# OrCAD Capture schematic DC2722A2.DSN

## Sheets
1 PAGE3: size B; title: DSP6713 SYSTEM; rev: V1.0; company: WITH DIGITAL POWER MANAGEMENT; note: DUAL STEP-DOWN uMODULE REGULATOR
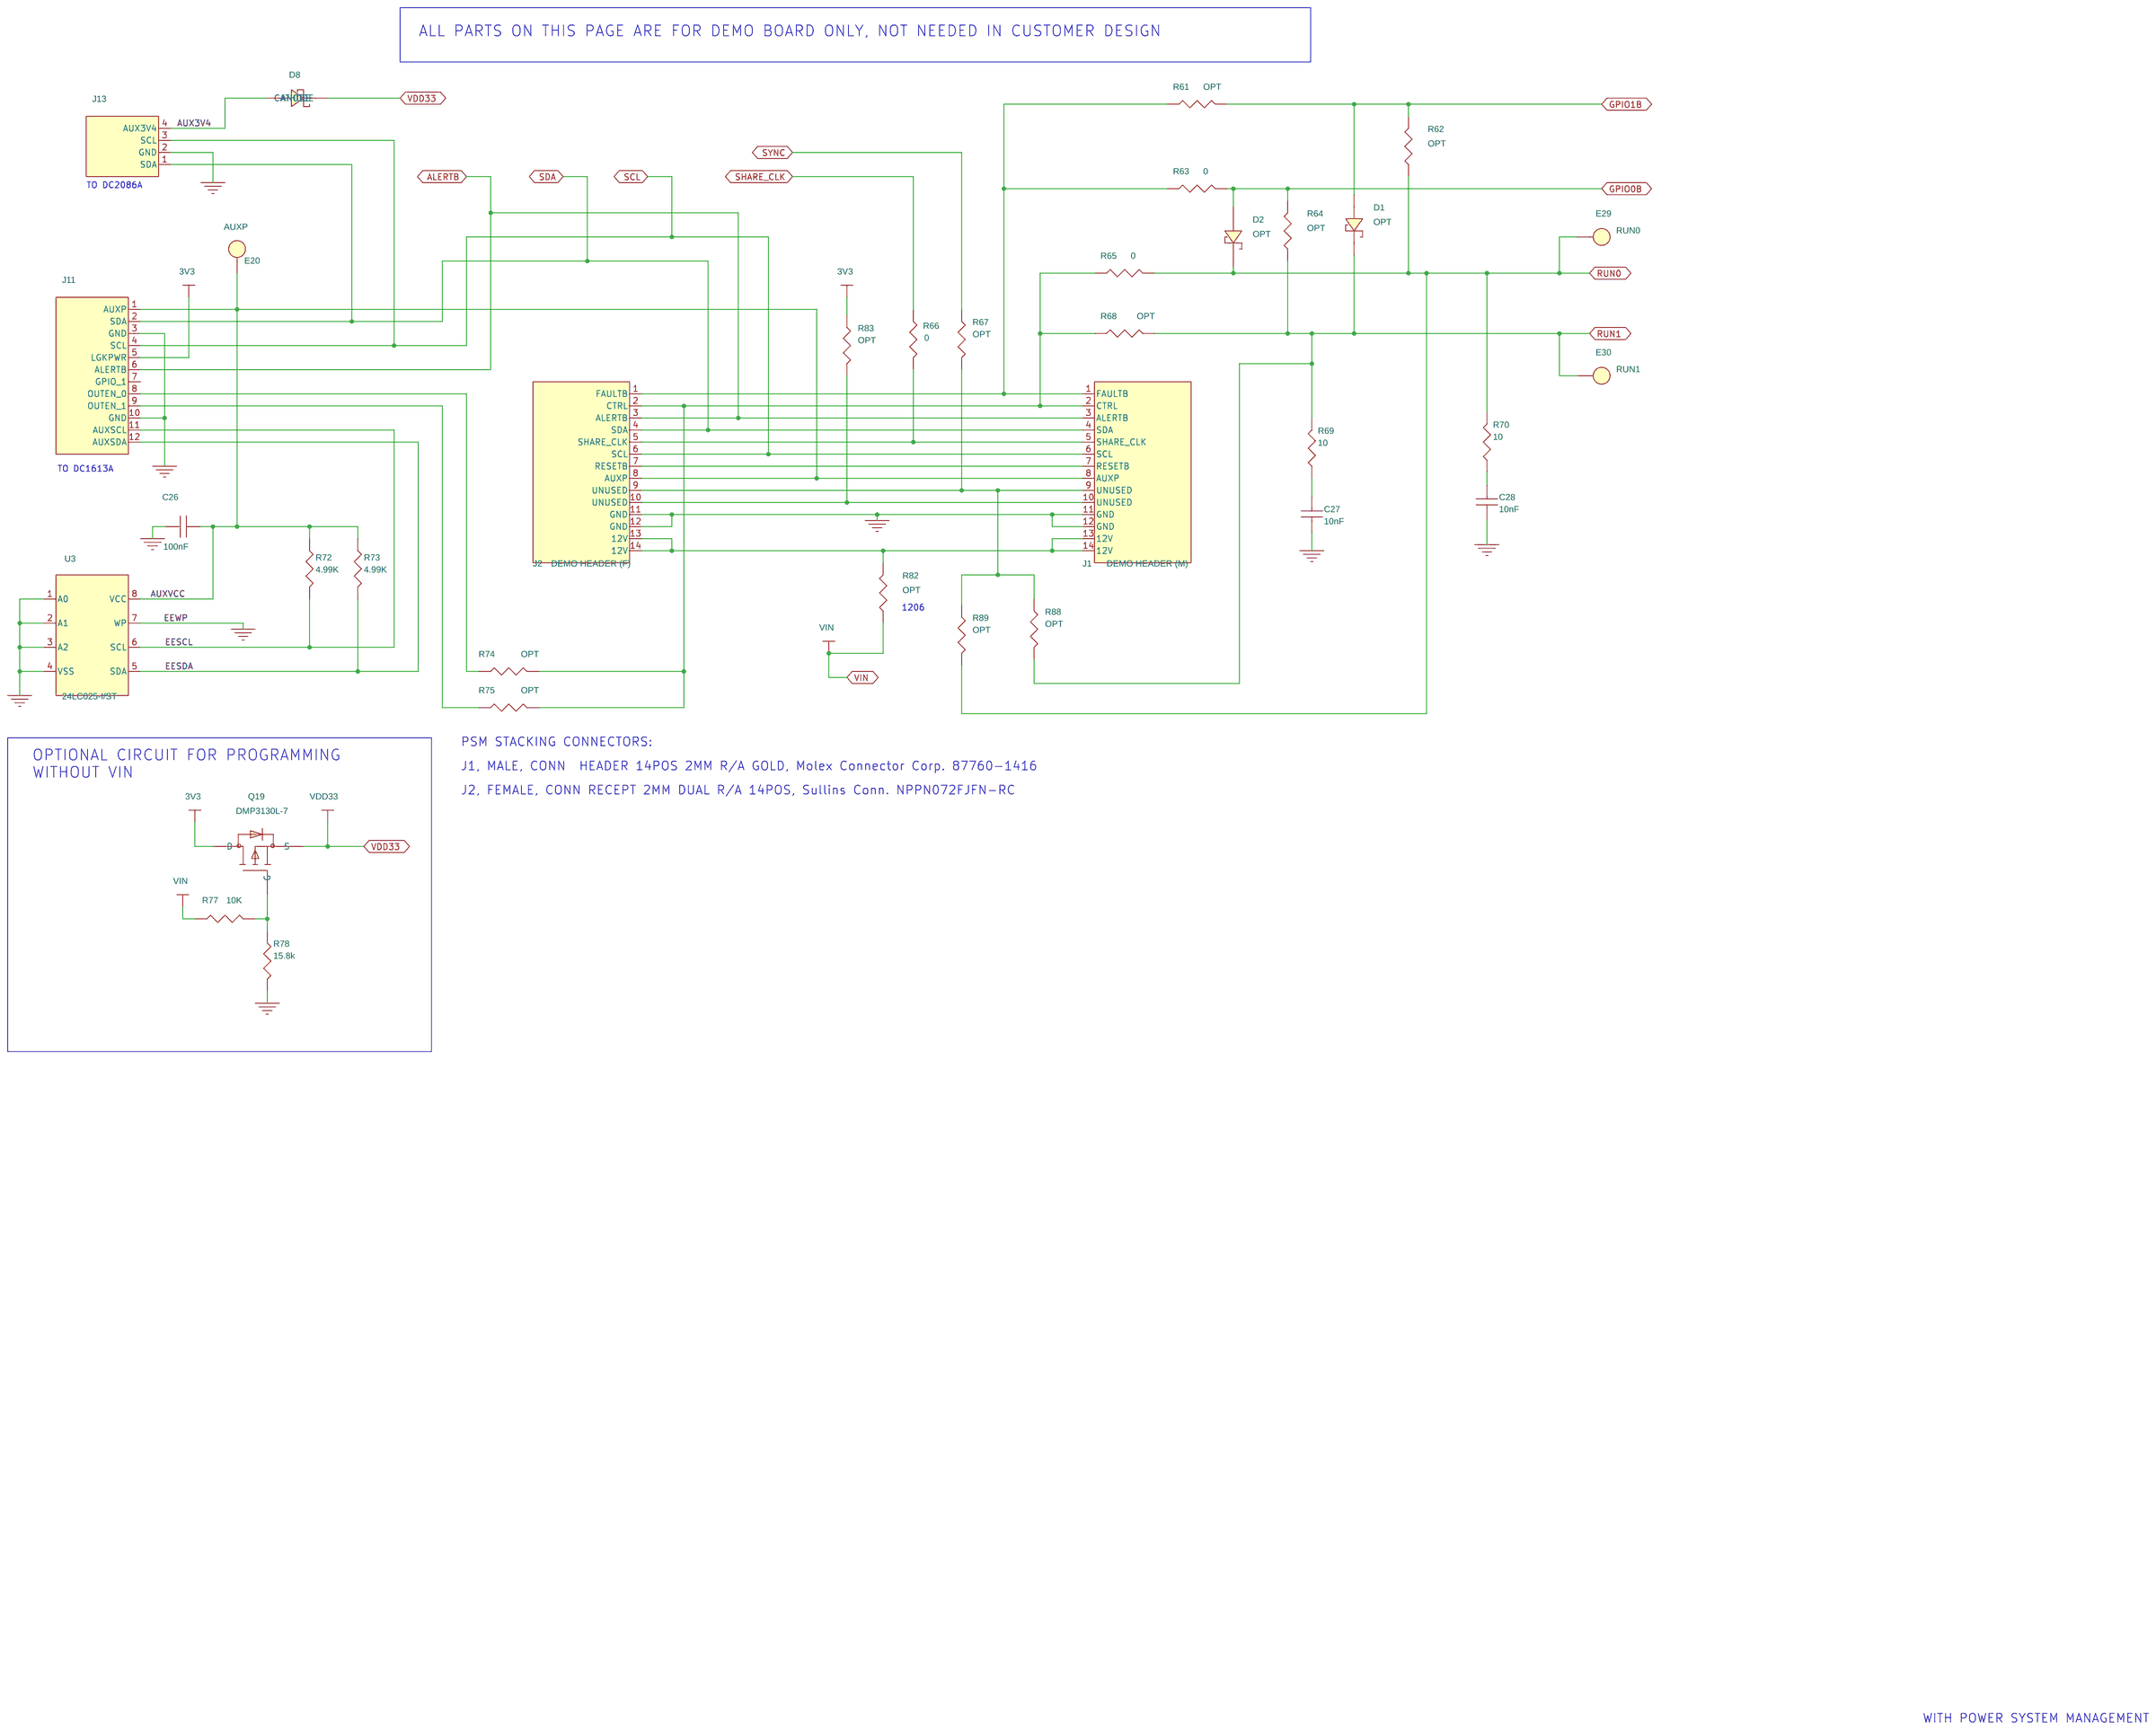
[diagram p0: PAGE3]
2 PAGE1: size C
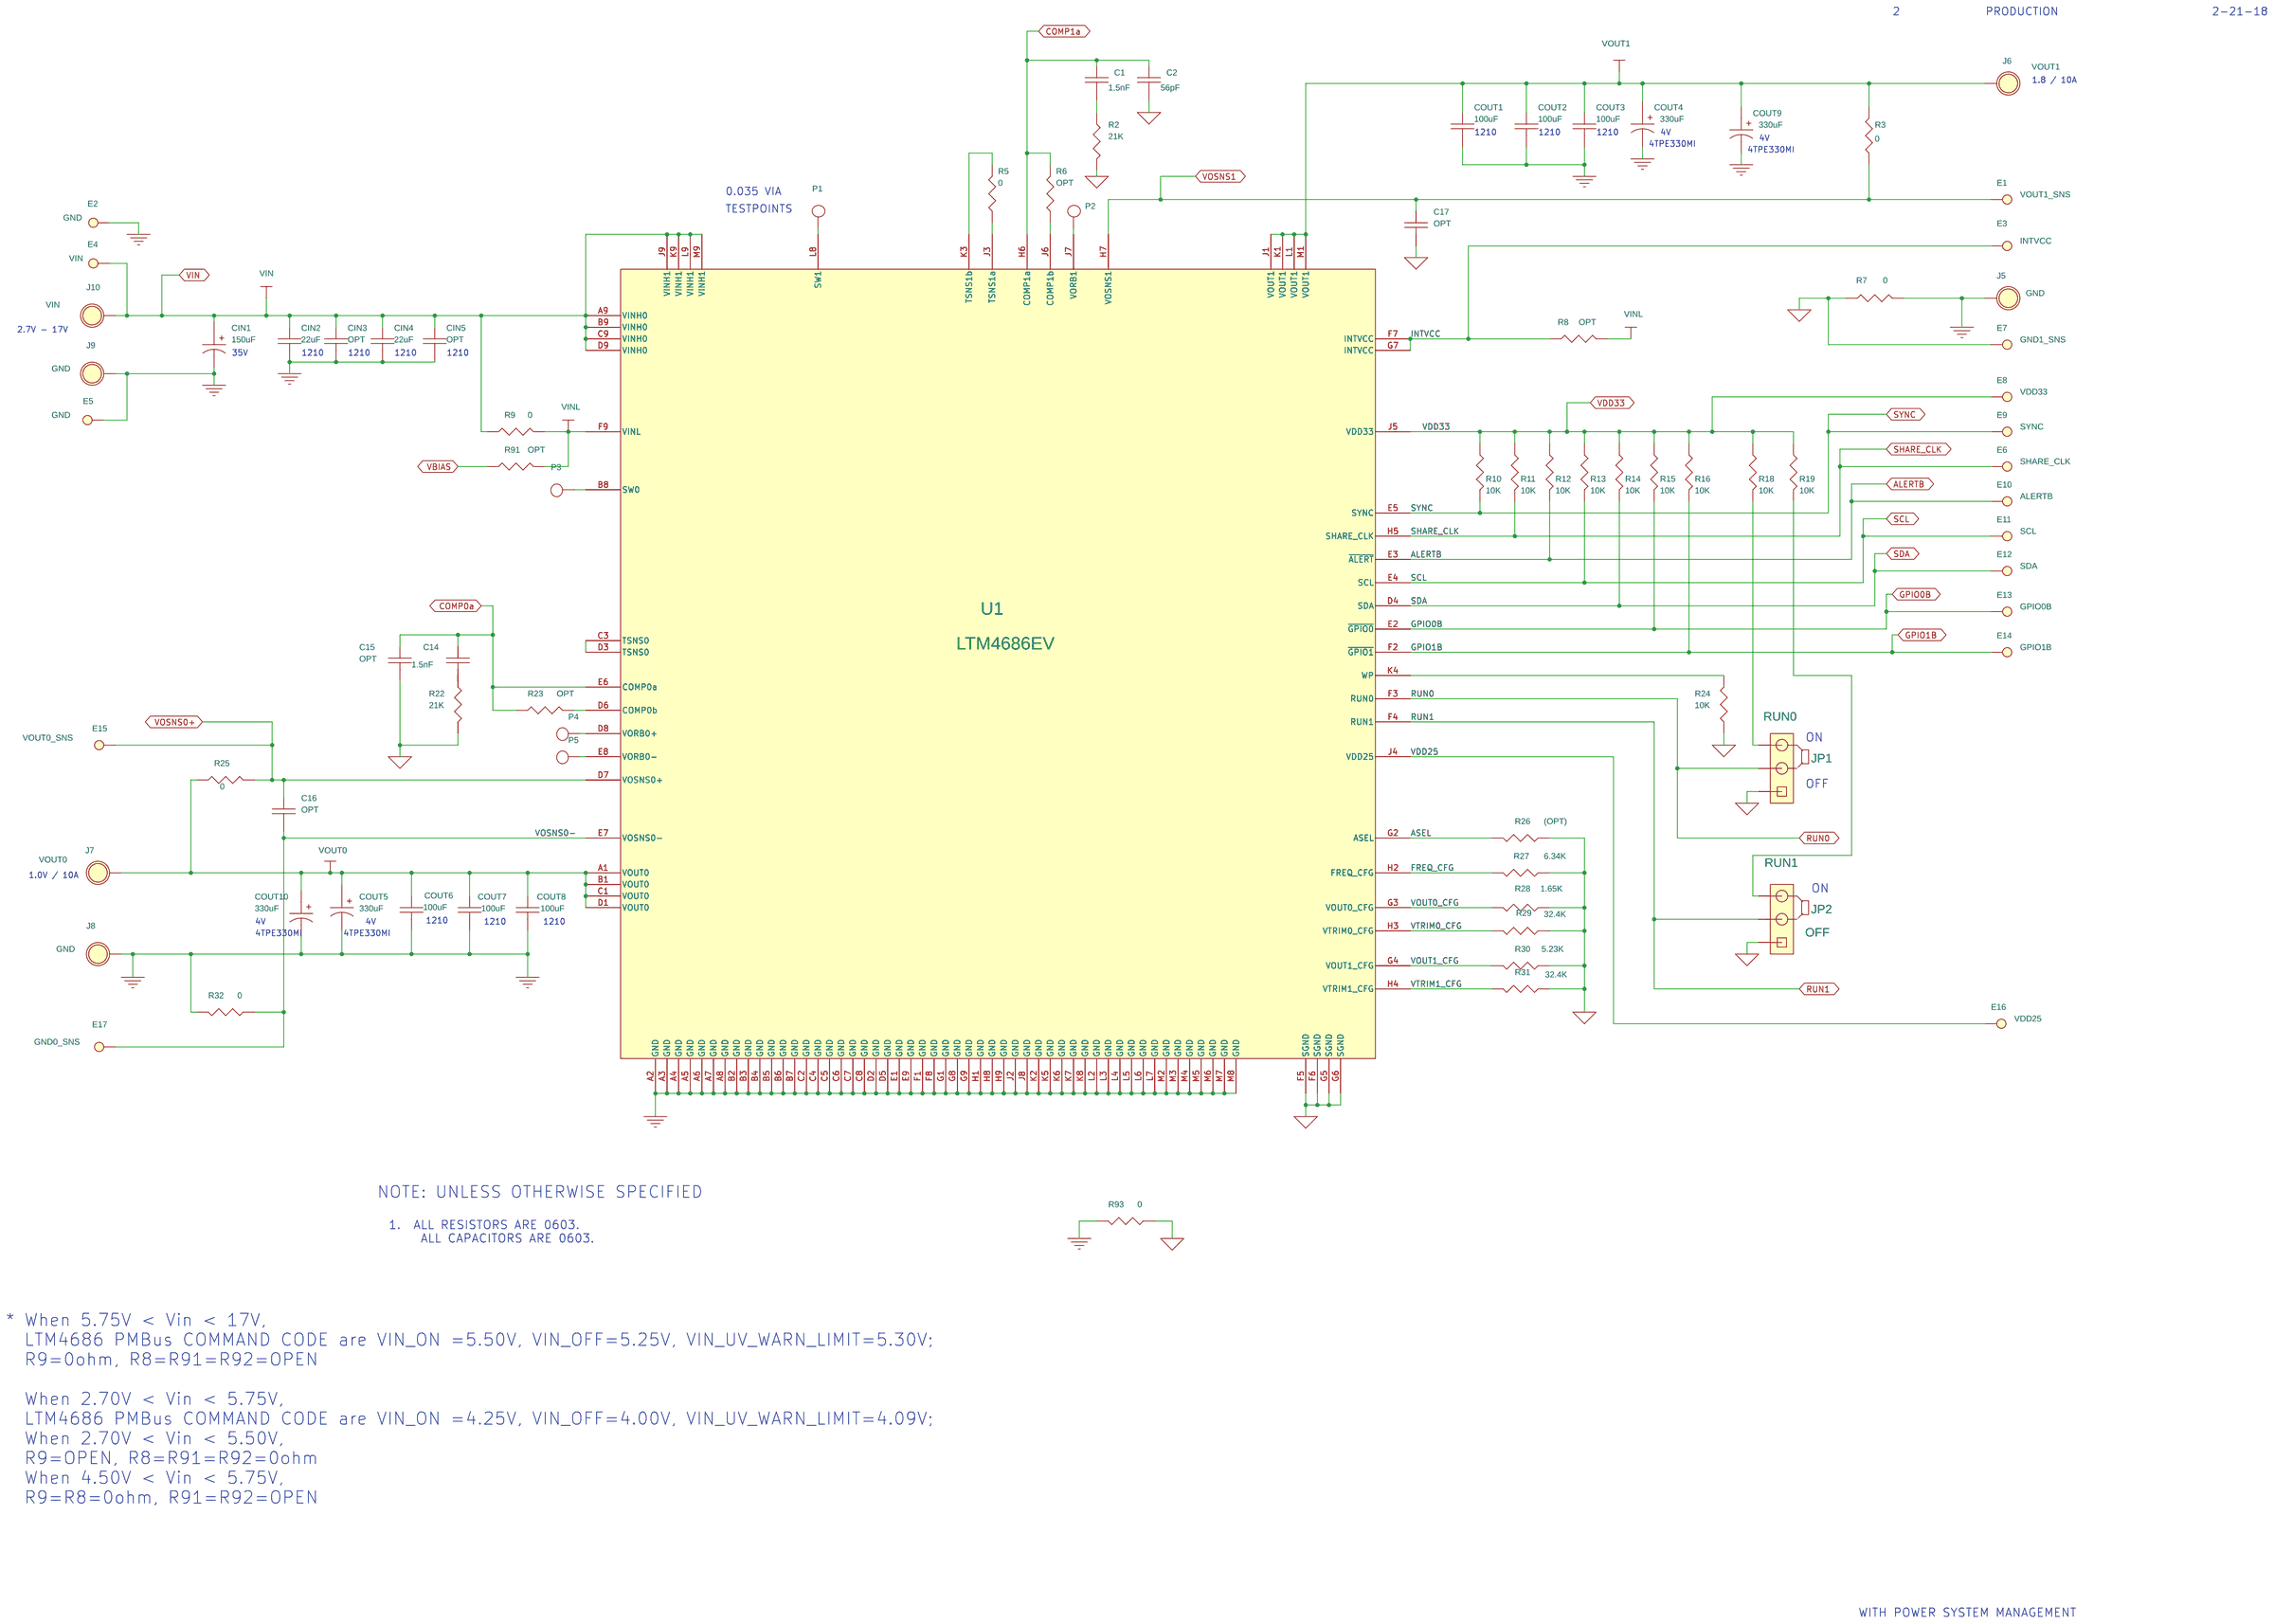
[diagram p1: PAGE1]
3 PAGE2: size Custom
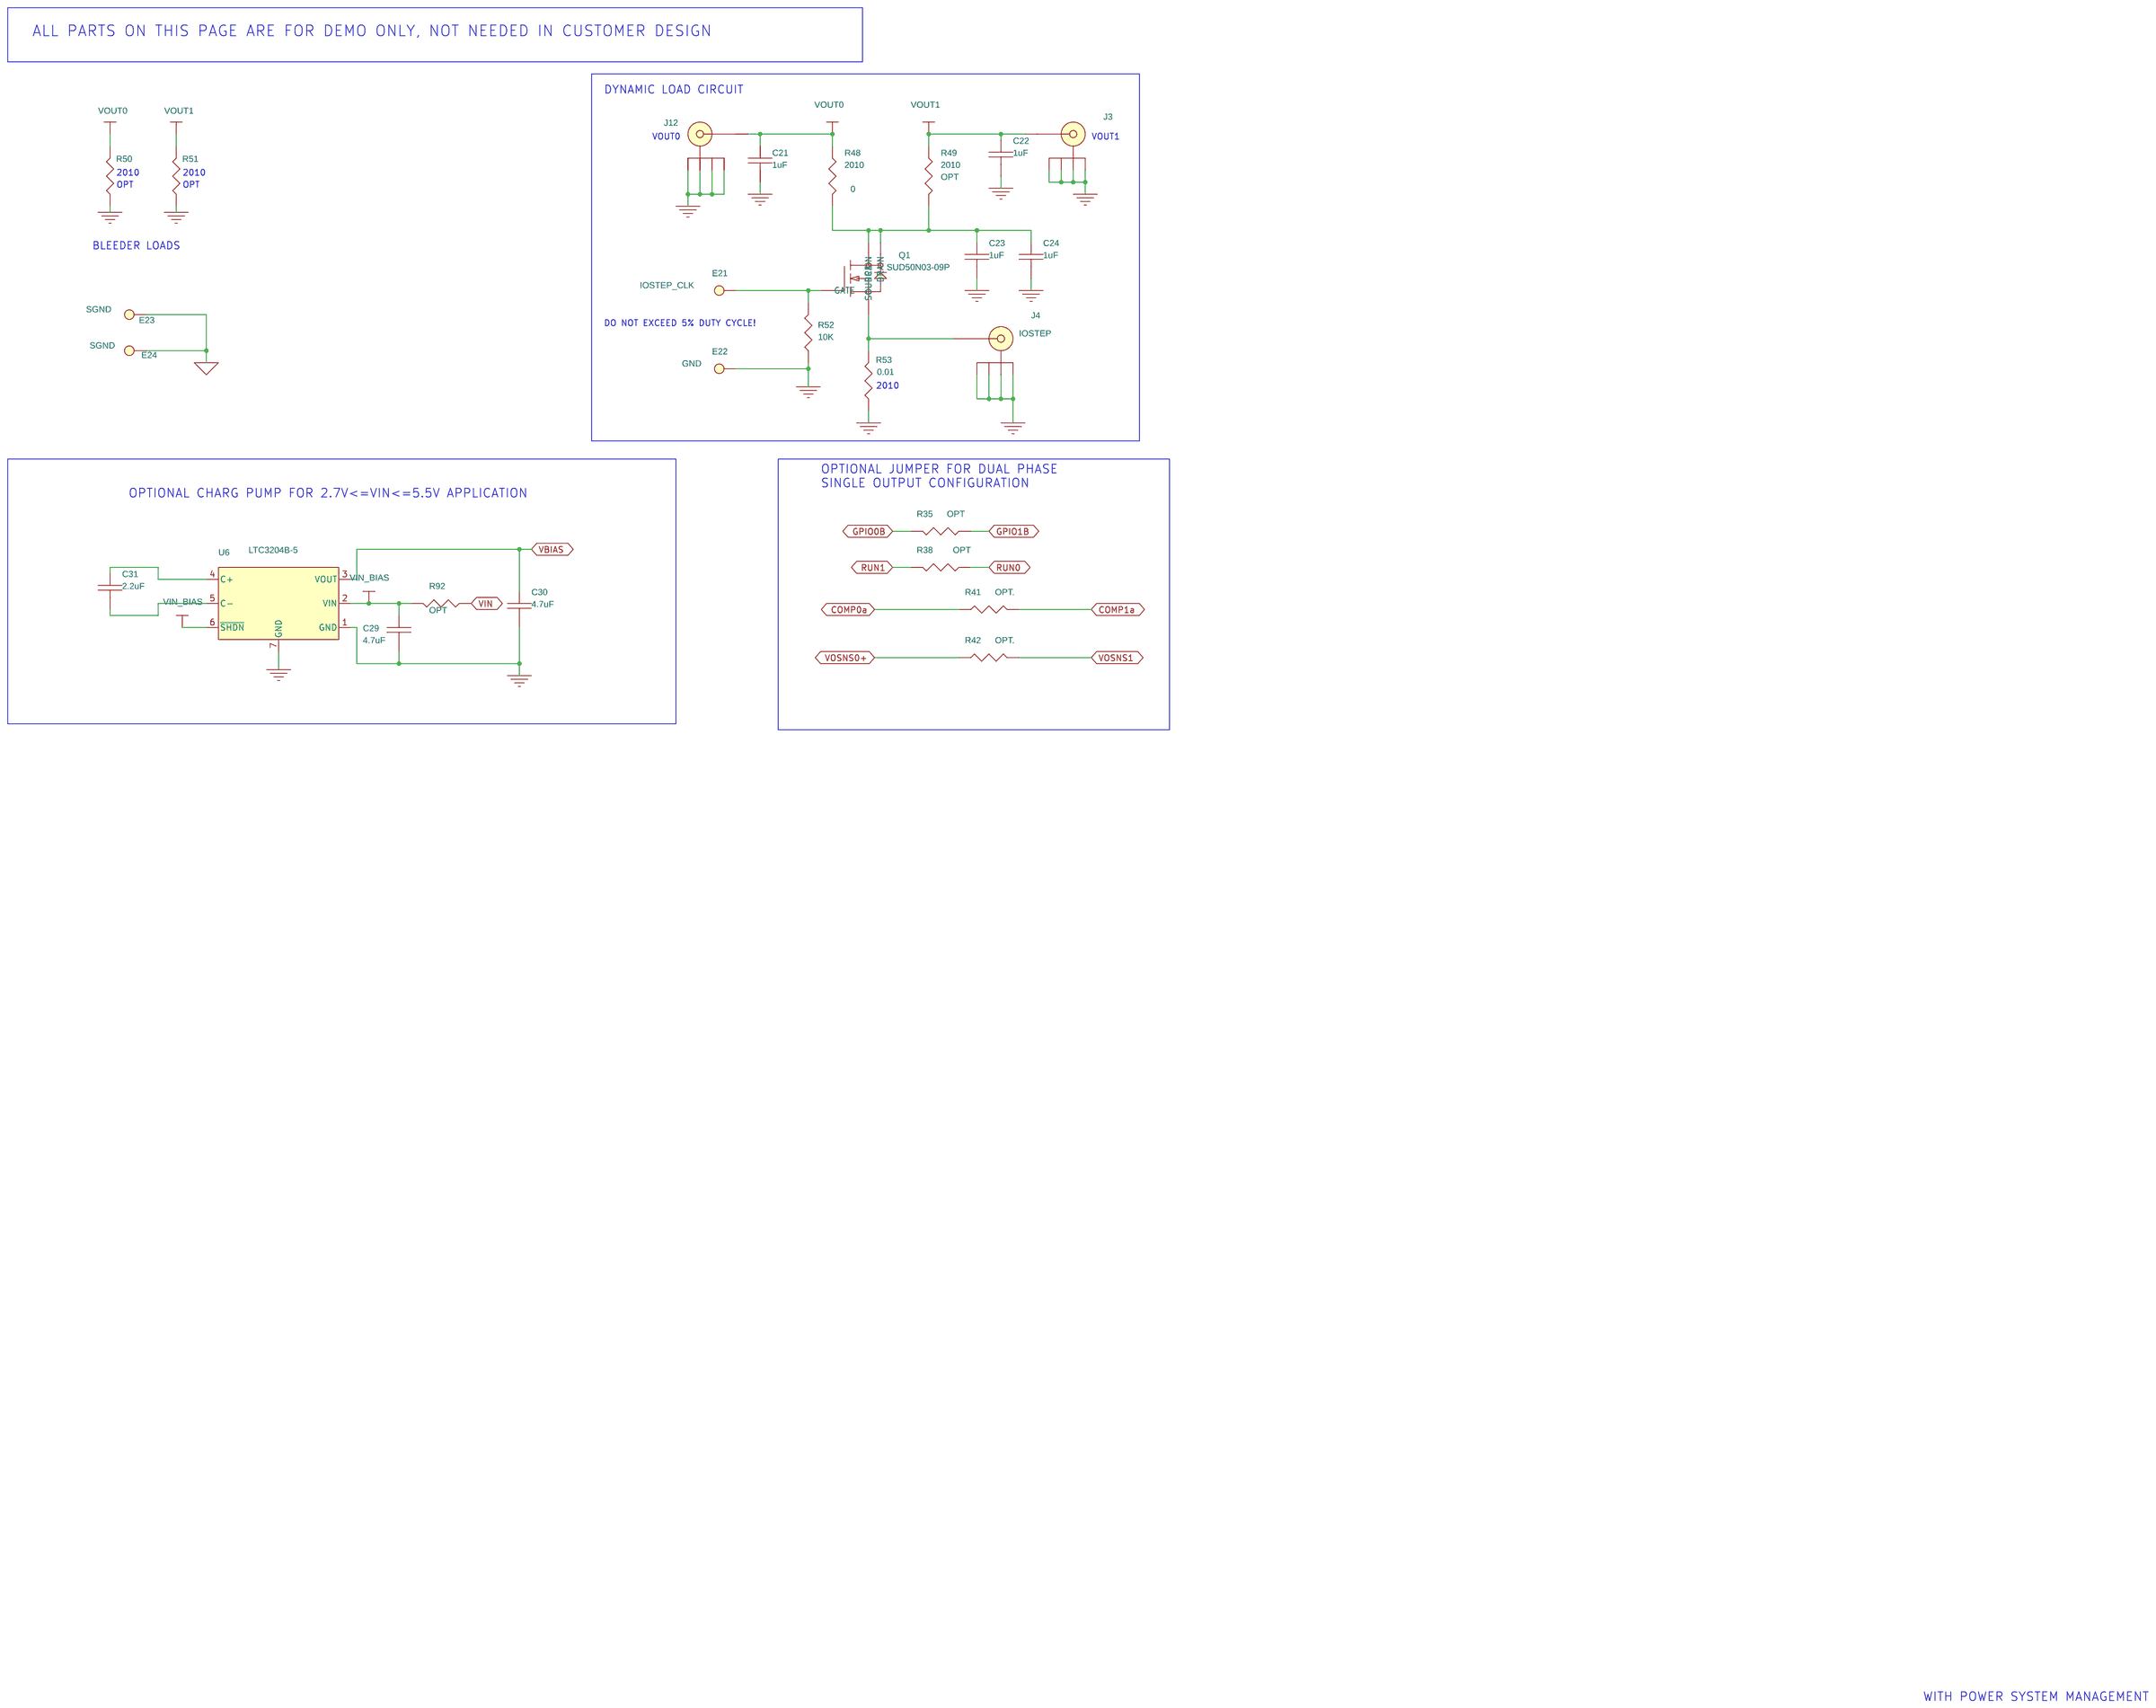
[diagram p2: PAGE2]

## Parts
sheet PAGE1
C1  1.5nF  [0603]
C2  56pF  [0603]
C14  1.5nF  [0603]
C15  OPT  [0603]
C16  OPT  [0603]
C17  OPT  [0603]
CIN1  150uF  [SANYO\8X10]
CIN2  22uF  [1210]
CIN3  OPT  [1210]
CIN4  22uF  [1210]
CIN5  OPT  [1210]
COUT1  100uF  [1210]
COUT2  100uF  [1210]
COUT3  100uF  [1210]
COUT4  330uF  [D3L]
COUT5  330uF  [D3L]
COUT6  100uF  [1210]
COUT7  100uF  [1210]
COUT8  100uF  [1210]
COUT9  330uF  [D3L]
COUT10  330uF  [D3L]
E1  TURRETS  [TURRETS]
E2  GND  [TURRETS]
E3  INTVCC  [TURRETS]
E4  TURRETS  [TURRETS]
E5  GND  [TURRETS]
E6  TURRETS  [TURRETS]
E7  TURRETS  [TURRETS]
E8  VDD33  [TURRETS]
E9  TURRETS  [TURRETS]
E10  TURRETS  [TURRETS]
E11  TURRETS  [TURRETS]
E12  TURRETS  [TURRETS]
E13  TURRETS  [TURRETS]
E14  TURRETS  [TURRETS]
E15  TURRETS  [TURRETS]
E16  VDD25  [TURRETS]
E17  TURRETS  [TURRETS]
J5  BANANA SMALL  [KEY-575-4]
J6  BANANA SMALL  [KEY-575-4]
J7  BANANA SMALL  [KEY-575-4]
J8  BANANA SMALL  [KEY-575-4]
J9  BANANA SMALL  [KEY-575-4]
J10  BANANA SMALL  [KEY-575-4]
JP1  3 Pins 2mm Ctrs.  [commcon2802s03g2]
JP2  3 Pins 2mm Ctrs.  [commcon2802s03g2]
P1  TURRETS  [PAD]
P2  TURRETS  [PAD]
P3  TURRETS  [PAD]
P4  TURRETS  [PAD]
P5  TURRETS  [PAD]
R2  21K  [0603]
R3  0  [0603]
R5  0  [0603]
R6  OPT  [0603]
R7  0  [0603]
R8  OPT  [0603]
R9  0  [0603]
R10  10K  [0603]
R11  10K  [0603]
R12  10K  [0603]
R13  10K  [0603]
R14  10K  [0603]
R15  10K  [0603]
R16  10K  [0603]
R18  10K  [0603]
R19  10K  [0603]
R22  21K  [0603]
R23  OPT  [0603]
R24  10K  [0603]
R25  0  [0603]
R26  (OPT)  [0603]
R27  6.34K  [0603]
R28  1.65K  [0603]
R29  32.4K  [0603]
R30  5.23K  [0603]
R31  32.4K  [0603]
R32  0  [0603]
R91  OPT  [0603]
R93  0  [0603]
U1  LTM4686EV  [BGA-108PIN-(16MMX11.9MMX3.51MM)]
XJP1  2mm Ctrs.
XJP2  2mm Ctrs.
sheet PAGE2
C21  1uF  [0603]
C22  1uF  [0603]
C23  1uF  [0805]
C24  1uF  [0603]
C29  4.7uF  [0603]
C30  4.7uF  [0603]
C31  2.2uF  [0603]
E21  IOSTEP_CLK  [TURRETS]
E22  GND  [TURRETS]
E23  SGND  [TURRETS]
E24  SGND  [TURRETS]
J3  XXX  [BNC]
J4  IOSTEP  [BNC]
J12  XXX  [BNC]
Q1  SUD50N03-09P  [TO252]
R35  OPT  [0603]
R38  OPT  [0603]
R41  OPT.  [0603]
R42  OPT.  [0603]
R48  2010  [2010]
R49  2010  [2010]
R50  30  [2512SENSE]
R51  30  [2512SENSE]
R52  10K  [0603]
R53  0.01  [2010]
R92  OPT  [0603]
U6  LTC3204B-5  [DFN-2X2]
sheet PAGE3
C26  100nF  [0603]
C27  10nF  [0603]
C28  10nF  [0603]
D1  OPT  [SOD323]
D2  OPT  [SOD323]
D8  DIODE SCHOTTKY  [PMEG2005AEL]
E20  AUXP  [TURRETS]
E29  RUN0  [TURRETS]
E30  RUN1  [TURRETS]
J1  DEMO HEADER (M)  [NPPN072FJFN]
J2  DEMO HEADER (F)  [NPPN072FJFN-RC]
J11  HD2X6-079  [HD2X6-079-MOLEX]
J13  HD2X6-079-PMBUS_0  [DF3A-4P-2DSA]
Q19  DMP3130L-7  [SOT-23]
R61  OPT  [0603]
R62  OPT  [0603]
R63  0  [0603]
R64  OPT  [0603]
R65  0  [0603]
R66  0  [0603]
R67  OPT  [0603]
R68  OPT  [0603]
R69  10  [0603]
R70  10  [0603]
R72  4.99K  [0603]
R73  4.99K  [0603]
R74  OPT  [0603]
R75  OPT  [0603]
R77  10K  [0603]
R78  15.8k  [0603]
R82  OPT  [1206]
R83  OPT  [0603]
R88  OPT  [0603]
R89  OPT  [0603]
U3  24LC025-I/ST  [TSSOP-8_4.4MM]

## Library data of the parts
C1 C2 C14-C17 = CAP0603_1: Component: cap; Manufacturer: TDK; Manufacturer P/N: C1608C0G1H102J; Tolerance: 5%; Type: cer 0603; Vendor: Digikey; Vendor P/N: 445-1293-1-ND; Volts/Amps/Watts: 50V
CIN1 = CAPR12X5_0: Component: cap; Manufacturer: SANYO; Tolerance: 20%; Type: OS-CON; Volts/Amps/Watts: 16V
CIN2-CIN5 = CAP1210_1: Component: cap; Manufacturer: Taiyo Yuden; Manufacturer P/N: GMK325BJ106KN-T; Tolerance: 10%; Type: cer 1210; Vendor: Digikey; Vendor P/N: 587-1439-1-ND; Volts/Amps/Watts: 35V
COUT1 = CAP0603_1: Component: cap; Manufacturer: TDK; Manufacturer P/N: C3225X5R0J107M; Tolerance: 20%; Type: cer 1210 X5R; Vendor: Digikey; Vendor P/N: 445-1437-1-ND; Volts/Amps/Watts: 6.3v
COUT2 COUT3 COUT6-COUT8 = CAP0603_1: Component: cap; Manufacturer: TDK; Manufacturer P/N: C3225X5R0J107M; Part Type: CAP1210; Tolerance: 20%; Type: cer 1210 X5R; Vendor: Digikey; Vendor P/N: 445-1437-1-ND; Volts/Amps/Watts: 6.3v
COUT4 COUT5 COUT9 COUT10 = CAPR12X5_0: Component: cap; Manufacturer: SANYO; Manufacturer P/N: 6TPF330M9L; Tolerance: 20%; Type: TANT; Volts/Amps/Watts: 6.3V
E1 = TURRETS_1: Component: tp; Label: VOUT1_SNS; Vendor: Digikey; Vendor P/N: 1593-2K-ND
E2 E5 E22 = TURRETS_1: Component: tp; Manufacturer: Keystone; Manufacturer P/N: 1593-2; Vendor: Digikey; Vendor P/N: 1593-2K-ND
E3 E8 E16 E21 E23 E24 = TURRETS_1: Component: tp; Label: GND; Manufacturer: Keystone; Manufacturer P/N: 1593-2; Vendor: Digikey; Vendor P/N: 1593-2K-ND
E4 = TURRETS_1: Component: tp; Label: VIN; Manufacturer: Keystone; Manufacturer P/N: 1593-2; Vendor: Digikey; Vendor P/N: 1593-2K-ND
E6 = TURRETS_1: Component: tp; Label: SHARE_CLK; Manufacturer: Keystone; Manufacturer P/N: 1593-2; Vendor: Digikey; Vendor P/N: 1593-2K-ND
E7 = TURRETS_1: Component: tp; Label: GND1_SNS; Vendor: Digikey; Vendor P/N: 1593-2K-ND
E9 = TURRETS_1: Component: tp; Label: SYNC; Manufacturer: Keystone; Manufacturer P/N: 1593-2; Vendor: Digikey; Vendor P/N: 1593-2K-ND
E10 = TURRETS_1: Component: tp; Label: ALERTB; Manufacturer: Keystone; Manufacturer P/N: 1593-2; Vendor: Digikey; Vendor P/N: 1593-2K-ND
E11 = TURRETS_1: Component: tp; Label: SCL; Manufacturer: Keystone; Manufacturer P/N: 1593-2; Vendor: Digikey; Vendor P/N: 1593-2K-ND
E12 = TURRETS_1: Component: tp; Label: SDA; Manufacturer: Keystone; Manufacturer P/N: 1593-2; Vendor: Digikey; Vendor P/N: 1593-2K-ND
E13 = TURRETS_1: Component: tp; Label: GPIO0B; Manufacturer: Keystone; Manufacturer P/N: 1593-2; Vendor: Digikey; Vendor P/N: 1593-2K-ND
E14 = TURRETS_1: Component: tp; Label: GPIO1B; Manufacturer: Keystone; Manufacturer P/N: 1593-2; Vendor: Digikey; Vendor P/N: 1593-2K-ND
E15 = TURRETS_1: Component: tp; Label: VOUT0_SNS; Vendor: Digikey; Vendor P/N: 1593-2K-ND
E17 = TURRETS_1: Component: tp; Label: GND0_SNS; Vendor: Digikey; Vendor P/N: 1593-2K-ND
J5 J8 J9 = BANANA_SMALL_0: Component: conn; Label: GND
J6 = BANANA_SMALL_0: Component: conn; Label: VOUT1
J7 = BANANA_SMALL_0: Component: conn; Label: VOUT0
J10 = BANANA_SMALL_0: Component: conn; Label: VIN
JP1 = Commcon2802s03g2_7: 11th Part Field: OFF; 12th Part Field: RUN0; 9th Part Field: ON
JP2 = Commcon2802s03g2_7: 11th Part Field: OFF; 12th Part Field: RUN1; 9th Part Field: ON
P1-P5 = PAD_2: Component: tp; Label: <Label>; Vendor: Digikey; Vendor P/N: 1593-2K-ND
R2 R22 = RES0603_9: Component: res; Label: <label>; Manufacturer: Panasonic; Manufacturer P/N: ERJ-3EKF5901V; Tolerance: 1%; Vendor: Digikey; Vendor P/N: P5.90KHCT-ND; Volts/Amps/Watts: 0.1W
R3 R5 R6 R23 = RES0603_9: Manufacturer: Rohm; Manufacturer P/N: RHM0.0GCT-ND; Tolerance: 5%; Vendor: Digikey; Vendor P/N: RHM0.0GCT-ND; Volts/Amps/Watts: 0.1W
R7 R9 R41 R42 R91 = RES0603_3
R8 = RES0603_9: Label: OPT 0; Manufacturer: Rohm; Manufacturer P/N: RHM0.0GCT-ND; Vendor: Digikey
R10-R16 R18 R19 R24 R29 R30 = RES0603_9: Manufacturer: ROHM; Manufacturer P/N: MCR03EZPFX1002; Vendor: Digikey; Vendor P/N: RHM10.0KHCT-ND; Volts/Amps/Watts: 0.1W
R25 = RES0603_9: Manufacturer: Rohm; Manufacturer P/N: MCR03EZPFX1000; Vendor: Digikey; Vendor P/N: RHM100HCT-ND; Volts/Amps/Watts: 0.1W
R26 R27 = RES0603_9: Manufacturer: Panasonic; Manufacturer P/N: ERJ-3EKF2002V; Vendor: Digikey; Vendor P/N: P20.0KHCT-ND; Volts/Amps/Watts: 0.1W
R28 = RES0603_9: Manufacturer: Panasonic; Manufacturer P/N: ERJ-3EKF1000V; Vendor: Digikey; Vendor P/N: P100HCT-ND; Volts/Amps/Watts: 0.1W
R31 = RES0603_9: Manufacturer: Panasonic; Manufacturer P/N: ERJ-3EKF1021V; Vendor: Digikey; Vendor P/N: P1.02KHCT-ND; Volts/Amps/Watts: 0.1W
R32 R93 = RES0603_9: Manufacturer: Yageo; Manufacturer P/N: RC0603JR-070RL; Tolerance: 5%; Vendor: Digikey; Vendor P/N: 311-0.0GRCT-ND; Volts/Amps/Watts: 0.1W
U1 = LTC3880-M0001_21: Component: IC; Manufacturer: LTC; Manufacturer P/N: LTC3880_M0001; Vendor: LTC; Vendor P/N: LTC3880_M0001
XJP1 XJP2 = CommconCCIJ2MM-138G
C21 C22 C24 = CAP0603_1
C23 C29-C31 = CAP1206_1: Manufacturer: Kemet; Manufacturer P/N: C1206C106K8RACTU; Tolerance: 10%; Type: cer 1206 X7R; Vendor: Digikey; Vendor P/N: 399-4937-1-ND; Volts/Amps/Watts: 10V
J3 J12 = BNC5-SCH_0: CONN,BNC,5 PINS; Part Number: CONNEX 112404
J4 = BNC5-SCH_0
Q1 = IRF540_0
R35 R38 = RES0603_9: Label: OPT 0; Manufacturer: Rohm; Manufacturer P/N: RHM0.0GCT-ND; Tolerance: 5%; Vendor: Digikey; Vendor P/N: RHM0.0GCT-ND; Volts/Amps/Watts: 0.1W
R48 = RES2512_0: Tolerance: 0
R49 = RES2512_0: Tolerance: OPT
R50 = RES0603_5: Label: 1W; Manufacturer: VISHAY; Manufacturer P/N: CRCW251230R0JNEG; Tolerance: 5%; Vendor: Digikey; Vendor P/N: 541-30XCT-ND; Volts/Amps/Watts: 0.1W
R51 = RES0603_6: Label: 1W; Tolerance: 5%; Vendor: Digikey; Vendor P/N: 541-30XCT-ND; Volts/Amps/Watts: 0.1W
R52 R92 = RES0603_9
R53 = RES0603_5: Label: 1W; Manufacturer: VISHAY; Manufacturer P/N: CRCW251230R0JNEG; Part Type: 2512; Tolerance: 5%; Vendor: Digikey; Vendor P/N: 541-30XCT-ND; Volts/Amps/Watts: 0.1W
U6 = LT1129CS8-3_2.3
C26 = CAP_NP: CAP, 0603 100nF 20% 16V X7R; Part Number: AVX 0603YC104MAT2A
C27 C28 = CAP_NP: CAP, 0603 10nF 10% 25V X7R; Part Number: AVX 06033C103KAT2A
D1 D2 = DIODE_SCHOTTKY_9: DIODE, SCHOTTKY 30V, 100mA; Part Number: CENTRAL SEMI CMDSH-3-TR
D8 = DIODE_SCHOTTKY_0
E20 E29 E30 = E_0: TURRET; Part Number: MILL MAX 2501-2-00-80-00-00-07-0
J1 = PMBUS_CONNECTOR20_3: CONN, SOCKET 20PIN  DUAL ROW R/A; Component: con; Manufacturer: Mill Max; Manufacturer P/N: 803-93-020-20-001; Part Number: MILL MAX 803-93-020-20-001; Type: conn  RA 20 dual row; Vendor: LTC; Vendor P/N: 803-93-020-20-001
J2 = PMBUS_HEADER20_3: HEADER, 20PIN DUAL ROW R/A; Component: con; Manufacturer: Mill Max; Manufacturer P/N: 802-40-020-20-0001; Part Number: MILL MAX 802-40-020-20-0001; Type: header RA 20 dual row; Vendor: LTC; Vendor P/N: 802-40-020-20-001
J11 = HD2X6-079-PMBUS_2: HEADER, 12PIN 2mm STR DL; Label: DC1427A HEADER; Manufacturer: MOLEX; Manufacturer P/N: 87831-1220; Part Number: FCI 98414-G06-12ULF; Type: header 12POS 2MM VERT; Vendor: Digikey; Vendor P/N: WM18561-ND
J13 = HD2X6-079-PMBUS_4: HEADER, 4PIN 2mm STR DL; Manufacturer: Hirose; Type: header 4POS 2MM VERT
Q19 = P-MOSFET: XSTR, N-CHANNEL DMOS FET; Part Number: VISHAY TP0101K-T1-E3
R61 R63 R65 R68 = RES0603_0: RES, 0603 0 OHMS JUMPER; Label: OPT 0; Manufacturer: Rohm; Manufacturer P/N: RHM0.0GCT-ND; Part Number: VISHAY CRCW06030000Z0EA; Tolerance: 5%; Vendor: Digikey; Vendor P/N: RHM0.0GCT-ND; Volts/Amps/Watts: 0.1W
R62 R64 R67 R75 R83 R88 R89 = RES0603_0: RES, 0603 OPTION; Label: OPT 0; Manufacturer: Rohm; Manufacturer P/N: RHM0.0GCT-ND; Part Number: OPTION; Tolerance: 5%; Vendor: Digikey; Vendor P/N: RHM0.0GCT-ND; Volts/Amps/Watts: 0.1W
R66 = RES0603_0: RES, 0603 0 OHMS JUMPER; Manufacturer: Rohm; Manufacturer P/N: RHM0.0GCT-ND; Part Number: VISHAY CRCW06030000Z0EA; Tolerance: 5%; Vendor: Digikey; Vendor P/N: RHM0.0GCT-ND; Volts/Amps/Watts: 0.1W
R69 R70 = RES0603_1: RES, 0603 10 OHMS 5% 1/10W; Manufacturer: Rohm; Manufacturer P/N: RHM0.0GCT-ND; Part Number: VISHAY CRCW060310R0JNEA; Tolerance: 5%; Vendor: Digikey; Vendor P/N: RHM0.0GCT-ND; Volts/Amps/Watts: 0.1W
R72 R73 = RES0603_0: RES, 0603 4.99K OHMS 1% 1/10W; Manufacturer: ROHM; Manufacturer P/N: MCR03EZPFX4991; Part Number: VISHAY CRCW06034K99FKEA; Vendor: Digikey; Vendor P/N: RHM4.99KHCT-ND; Volts/Amps/Watts: 0.1w
R74 R82 = RES0603_3: RES, 0603 OPTION; Label: OPT 0; Manufacturer: Rohm; Manufacturer P/N: RHM0.0GCT-ND; Part Number: OPTION; Tolerance: 5%; Vendor: Digikey; Vendor P/N: RHM0.0GCT-ND; Volts/Amps/Watts: 0.1W
R77 = RES0603_11: RES, 0603 10K OHMS 5% 1/10W; Part Number: VISHAY CRCW060310K0JNEA
R78 = RES0603_11: RES, 0603 15.8K OHMS 1% 1/10W; Part Number: VISHAY CRCW060315K8FKEA
U3 = 24LC025-I_SN: IC, 24LC05-I/ST; Part Number: MICROCHIP 24LC025-I/ST

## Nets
3V3: J11.5(LGKPWR) Q19.3(D) R83.1
GND_POWER: C21.2 C22.2 C23.2 C24.2 C26.2 C27.2 C28.2 C29.2 C30.2 CIN1.2 CIN2.2 CIN3.2 CIN4.2 CIN5.2 COUT1.2 COUT2.2 COUT3.2 COUT4.2 COUT5.2 COUT6.2 COUT7.2 COUT8.2 COUT9.2 COUT10.2 E2.1(TP) E5.1(TP) E22.1(TP) J1.11(GND) J1.12(GND) J2.11(GND) J2.12(GND) J3.2 J3.3 J3.4 J3.5 J4.2 J4.3 J4.4 J4.5 J5.1(TP) J8.1(TP) J9.1(TP) J11.3(GND) J11.10(GND) J12.2 J12.3 J12.4 J12.5 J13.2(GND) R7.2 R32.2 R50.1 R51.1 R52.2 R53.1 R78.2 R93.2 U1.A2(GND) U1.A3(GND) U1.A4(GND) U1.A5(GND) U1.A6(GND) U1.A7(GND) U1.A8(GND) U1.B2(GND) U1.B3(GND) U1.B4(GND) U1.B5(GND) U1.B6(GND) U1.B7(GND) U1.C2(GND) U1.C4(GND) U1.C5(GND) U1.C6(GND) U1.C7(GND) U1.C8(GND) U1.D2(GND) U1.D5(GND) U1.E1(GND) U1.E9(GND) U1.F1(GND) U1.F8(GND) U1.G1(GND) U1.G8(GND) U1.G9(GND) U1.H1(GND) U1.H8(GND) U1.H9(GND) U1.J2(GND) U1.J8(GND) U1.K2(GND) U1.K5(GND) U1.K6(GND) U1.K7(GND) U1.K8(GND) U1.L2(GND) U1.L3(GND) U1.L4(GND) U1.L5(GND) U1.L6(GND) U1.L7(GND) U1.M2(GND) U1.M3(GND) U1.M4(GND) U1.M5(GND) U1.M6(GND) U1.M7(GND) U1.M8(GND) U3.1(A0) U3.2(A1) U3.3(A2) U3.4(VSS) U3.7(WP) U6.1(GND) U6.7(GND)
GND_SIGNAL: C2.2 C15.2 C17.2 E7.1(TP) E23.1(TP) E24.1(TP) JP1.1 JP2.1 R2.2 R7.1 R22.2 R24.1 R26.1 R27.1 R28.1 R29.1 R30.1 R31.1 R93.1 U1.F5(SGND) U1.F6(SGND) U1.G5(SGND) U1.G6(SGND)
VDD25: E16.1(TP) U1.J4(VDD25)
VDD33: D8.1(CATHODE) E8.1(TP) Q19.2(S) R10.1 R11.1 R12.1 R13.1 R14.1 R15.1 R16.1 R18.1 R19.1 U1.J5(VDD33)
VIN: CIN1.1 CIN2.1 CIN3.1 CIN4.1 CIN5.1 E4.1(TP) J10.1(TP) R9.1 R77.1 R82.1 R92.2 U1.A9(VINH0) U1.B9(VINH0) U1.C9(VINH0) U1.D9(VINH0) U1.J9(VINH1) U1.K9(VINH1) U1.L9(VINH1) U1.M9(VINH1)
VIN_BIAS: C29.1 R92.1 U6.2(VIN) U6.6(~{SHDN})
VINL: R8.1 R9.2 R91.2 U1.F9(VINL)
ALERTB: E10.1(TP) J1.3(ALERTB) J2.3(ALERTB) J11.6(ALERTB) R12.2 U1.E3(~{ALERT})
ASEL: R26.2 U1.G2(ASEL)
AUX3V4: D8.2(ANODE) J13.4(AUX3V4)
AUXVCC: C26.1 E20.1(A) J1.8(AUXP) J2.8(AUXP) J11.1(AUXP) R72.1 R73.1 U3.8(VCC)
COMP0a: C14.1 C15.1 R23.1 R41.1 U1.E6(COMP0a)
COMP1a: C1.1 C2.1 R6.2 R41.2 U1.H6(COMP1a)
EESCL: J11.11(AUXSCL) R72.2 U3.6(SCL)
EESDA: J11.12(AUXSDA) R73.2 U3.5(SDA)
FREQ_CFG: R27.2 U1.H2(FREQ_CFG)
GPIO0B: D2.2(ANODE) E13.1(TP) R15.2 R35.2 R63.2 R64.2 U1.E2(~{GPIO0})
GPIO1B: D1.2(ANODE) E14.1(TP) R16.2 R35.1 R61.2 R62.2 U1.F2(~{GPIO1})
INTVCC: E3.1(TP) R8.2 U1.F7(INTVCC) U1.G7(INTVCC)
RUN0: D2.1(CATHODE) E29.1(A) JP1.2 R38.2 R62.1 R65.2 R70.2 R89.2 U1.F3(RUN0)
RUN1: D1.1(CATHODE) E30.1(A) JP2.2 R38.1 R64.1 R68.2 R69.2 R88.2 U1.F4(RUN1)
SCL: E11.1(TP) J1.6(SCL) J2.6(SCL) J11.4(SCL) J13.3(SCL) R13.2 U1.E4(SCL)
SDA: E12.1(TP) J1.4(SDA) J2.4(SDA) J11.2(SDA) J13.1(SDA) R14.2 U1.D4(SDA)
SHARE_CLK: E6.1(TP) R11.2 R66.1 U1.H5(SHARE_CLK)
SYNC: E9.1(TP) R10.2 R67.1 U1.E5(SYNC)
VBIAS: C30.1 R91.1 U6.3(VOUT)
VOSNS0+: C16.1 E15.1(TP) R25.1 R42.1 U1.D7(VOSNS0+)
VOSNS0-: C16.2 E17.1(TP) R32.1 U1.E7(VOSNS0-)
VOSNS1: C17.1 E1.1(TP) R3.2 R42.2 U1.H7(VOSNS1)
VOUT0: C21.1 COUT5.1 COUT6.1 COUT7.1 COUT8.1 COUT10.1 J7.1(TP) J12.1 R25.2 R48.1 R50.2 U1.A1(VOUT0) U1.B1(VOUT0) U1.C1(VOUT0) U1.D1(VOUT0)
VOUT0_CFG: R28.2 U1.G3(VOUT0_CFG)
VOUT1: C22.1 COUT1.1 COUT2.1 COUT3.1 COUT4.1 COUT9.1 J3.1 J6.1(TP) R3.1 R49.1 R51.2 U1.J1(VOUT1) U1.K1(VOUT1) U1.L1(VOUT1) U1.M1(VOUT1)
VOUT1_CFG: R30.2 U1.G4(VOUT1_CFG)
VTRIM0_CFG: R29.2 U1.H3(VTRIM0_CFG)
VTRIM1_CFG: R31.2 U1.H4(VTRIM1_CFG)
N16779036: E21.1(TP) Q1.1(GATE) R52.1
N16779111: J4.1 Q1.3(SOURCE) R53.2
N16779469: C23.1 C24.1 Q1.2(DRAIN) Q1.4(DRAIN) R48.2 R49.2
N17002004: C14.2 R22.1
N17134921: P4.1(TP) U1.D8(VORB0+)
N17135374: P5.1(TP) U1.E8(VORB0-)
N17138086: R23.2 U1.D6(COMP0b)
N17139451: U1.C3(TSNS0) U1.D3(TSNS0)
N17154876: R6.1 U1.J6(COMP1b)
N17160063: P2.1(TP) U1.J7(VORB1)
N17162925: R5.1 U1.J3(TSNS1a)
N17163420: R5.2 U1.K3(TSNS1b)
N17166430: P1.1(TP) U1.L8(SW1)
N17299431: JP2.3 R19.2
N17491667: R24.2 U1.K4(WP)
N17755524: JP1.3 R18.2
N17988510: C1.2 R2.1
N18073508: P3.1(TP) U1.B8(SW0)
N18290233: J1.1(FAULTB) J2.1(FAULTB) R61.1 R63.1
N18290244: J11.8(OUTEN_0) R74.1
N18290245: J11.9(OUTEN_1) R75.1
N18290250: J1.2(CTRL) J2.2(CTRL) R65.1 R68.1 R74.2 R75.2
N18290295: C27.1 R69.1
N18290296: C28.1 R70.1
N18290320: Q19.1(G) R77.2 R78.1
N18290348: J1.5(SHARE_CLK) J2.5(SHARE_CLK) R66.2
N18290350: J1.7(RESETB) J2.7(RESETB)
N18290352: J1.9(UNUSED) J2.9(UNUSED) R67.2 R88.1 R89.1
N18290358: J1.13(12V) J1.14(12V) J2.13(12V) J2.14(12V) R82.2
N18290399: J1.10(UNUSED) J2.10(UNUSED) R83.2
N18390221: C31.1 U6.4(C+)
N18390235: C31.2 U6.5(C-)

Not connected (* = marked no-connect by the designer): J11 7(GPIO_1)

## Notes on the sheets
sheet 1
- ALL PARTS ON THIS PAGE ARE FOR DEMO BOARD ONLY, NOT NEEDED IN CUSTOMER DESIGN
- TO DC2086A
- TO DC1613A
- 1206
- PSM STACKING CONNECTORS:
- OPTIONAL CIRCUIT FOR PROGRAMMING
  WITHOUT VIN
- J1, MALE, CONN  HEADER 14POS 2MM R/A GOLD, Molex Connector Corp. 87760-1416
- J2, FEMALE, CONN RECEPT 2MM DUAL R/A 14POS, Sullins Conn. NPPN072FJFN-RC
- WITH POWER SYSTEM MANAGEMENT
sheet 2
- 2
- PRODUCTION
- 2-21-18
- 1.8 / 10A
- 1210
- 1210
- 1210
- 4V
- 4TPE330MI
- 4V
- 4TPE330MI
- 0.035 VIA
- TESTPOINTS
- 2.7V - 17V
- 35V
- 1210
- 1210
- 1210
- 1210
- ON
- OFF
- 1.0V / 10A
- ON
- 4V
- 4V
- 1210
- 1210
- 1210
- 4TPE330MI
- 4TPE330MI
- NOTE: UNLESS OTHERWISE SPECIFIED
- 1.  ALL RESISTORS ARE 0603.
       ALL CAPACITORS ARE 0603.
- * When 5.75V < Vin < 17V,
    LTM4686 PMBus COMMAND CODE are VIN_ON =5.50V, VIN_OFF=5.25V, VIN_UV_WARN_LIMIT=5.30V;
    R9=0ohm, R8=R91=R92=OPEN
    When 2.70V < Vin < 5.75V,
    LTM4686 PMBus COMMAND CODE are VIN_ON =4.25V, VIN_OFF=4.00V, VIN_UV_WARN_LIMIT=4.09V;
    When 2.70V < Vin < 5.50V,
    R9=OPEN, R8=R91=R92=0ohm
    When 4.50V < Vin < 5.75V,
    R9=R8=0ohm, R91=R92=OPEN
- WITH POWER SYSTEM MANAGEMENT
sheet 3
- ALL PARTS ON THIS PAGE ARE FOR DEMO ONLY, NOT NEEDED IN CUSTOMER DESIGN
- DYNAMIC LOAD CIRCUIT
- VOUT0
- VOUT1
- 2010
- 2010
- OPT
- OPT
- BLEEDER LOADS
- DO NOT EXCEED 5% DUTY CYCLE!
- 2010
- OPTIONAL JUMPER FOR DUAL PHASE
  SINGLE OUTPUT CONFIGURATION
- OPTIONAL CHARG PUMP FOR 2.7V<=VIN<=5.5V APPLICATION
- WITH POWER SYSTEM MANAGEMENT
